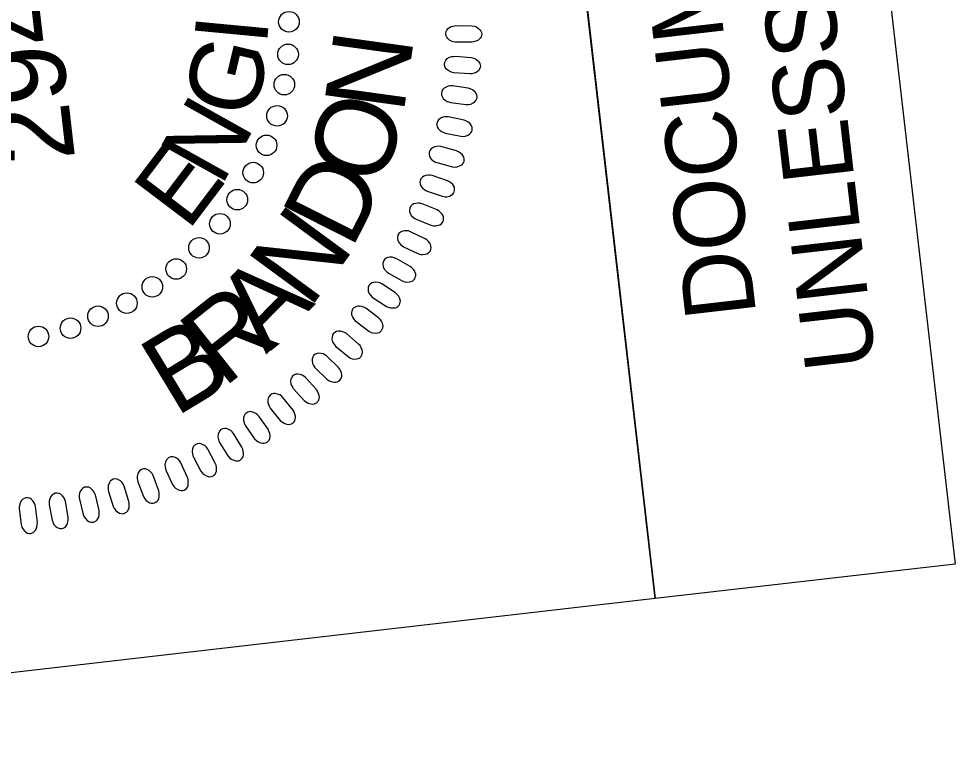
# Model space of a CAD drawing. Extents: x 477658 to 478938, y 495105 to 496902.
# Drawn here: x 477804.4 to 477877.3, y 496568.3 to 496626.4 of the extents above; entities that cross this region are included whole.
import ezdxf

# ---------------------------------------------------------------- set-up
doc = ezdxf.new("R2010")
doc.units = 0
for name, color, linetype in [('Sheet PE Seal Cell', 7, 'Continuous'), ('Sheet Plan CELL', 7, 'Continuous'), ('Sheet Sticker Exception Certification CELL', 7, 'Continuous')]:
    doc.layers.add(name, color=color, linetype=linetype)

msp = doc.modelspace()

# ---------------------------------------------------------------- linework, layer by layer
at = {"layer": 'Sheet PE Seal Cell'}
for points in [[(477838.441, 496625.837), (477839.667, 496625.823), (477839.886, 496625.783), (477840.025, 496625.729), (477840.194, 496625.615), (477840.302, 496625.517), (477840.381, 496625.404), (477840.419, 496625.299), (477840.438, 496625.186), (477840.417, 496625.075), (477840.386, 496624.955), (477840.325, 496624.851), (477840.223, 496624.748), (477840.143, 496624.689), (477839.993, 496624.623), (477839.813, 496624.565), (477839.653, 496624.545), (477838.397, 496624.551), (477838.227, 496624.576), (477838.088, 496624.623), (477837.93, 496624.713), (477837.791, 496624.827), (477837.713, 496624.925), (477837.654, 496625.083), (477837.636, 496625.233), (477837.678, 496625.382), (477837.729, 496625.486), (477837.83, 496625.612), (477838, 496625.729), (477838.181, 496625.795), (477838.311, 496625.823)], [(477838.388, 496623.449), (477839.611, 496623.358), (477839.827, 496623.305), (477839.963, 496623.242), (477840.124, 496623.118), (477840.225, 496623.012), (477840.297, 496622.895), (477840.329, 496622.788), (477840.34, 496622.674), (477840.312, 496622.564), (477840.273, 496622.447), (477840.206, 496622.347), (477840.099, 496622.25), (477840.015, 496622.196), (477839.861, 496622.14), (477839.677, 496622.094), (477839.516, 496622.083), (477838.263, 496622.169), (477838.095, 496622.204), (477837.96, 496622.259), (477837.807, 496622.36), (477837.676, 496622.482), (477837.603, 496622.585), (477837.556, 496622.746), (477837.547, 496622.897), (477837.598, 496623.042), (477837.655, 496623.144), (477837.763, 496623.263), (477837.942, 496623.369), (477838.126, 496623.423), (477838.257, 496623.443)], [(477838.009, 496619.86), (477839.224, 496619.692), (477839.445, 496619.7), (477839.592, 496619.732), (477839.775, 496619.82), (477839.897, 496619.901), (477839.991, 496620.002), (477840.045, 496620.1), (477840.08, 496620.208), (477840.075, 496620.322), (477840.062, 496620.445), (477840.018, 496620.556), (477839.933, 496620.673), (477839.862, 496620.744), (477839.723, 496620.83), (477839.553, 496620.914), (477839.398, 496620.958), (477838.154, 496621.138), (477837.983, 496621.138), (477837.839, 496621.112), (477837.669, 496621.045), (477837.515, 496620.954), (477837.423, 496620.868), (477837.342, 496620.721), (477837.302, 496620.576), (477837.321, 496620.421), (477837.356, 496620.311), (477837.437, 496620.172), (477837.589, 496620.03), (477837.758, 496619.939), (477837.882, 496619.892)], [(477837.607, 496617.465), (477838.81, 496617.222), (477839.032, 496617.215), (477839.179, 496617.238), (477839.368, 496617.314), (477839.495, 496617.388), (477839.595, 496617.483), (477839.655, 496617.576), (477839.697, 496617.683), (477839.699, 496617.797), (477839.694, 496617.92), (477839.656, 496618.034), (477839.578, 496618.157), (477839.512, 496618.231), (477839.379, 496618.327), (477839.215, 496618.421), (477839.063, 496618.475), (477837.833, 496618.731), (477837.662, 496618.743), (477837.517, 496618.726), (477837.343, 496618.67), (477837.184, 496618.588), (477837.086, 496618.508), (477836.996, 496618.367), (477836.947, 496618.224), (477836.956, 496618.069), (477836.985, 496617.957), (477837.057, 496617.813), (477837.199, 496617.662), (477837.362, 496617.56), (477837.483, 496617.506)], [(477836.964, 496615.168), (477838.149, 496614.849), (477838.371, 496614.828), (477838.519, 496614.842), (477838.712, 496614.907), (477838.843, 496614.972), (477838.949, 496615.06), (477839.015, 496615.15), (477839.063, 496615.254), (477839.073, 496615.367), (477839.075, 496615.491), (477839.045, 496615.607), (477838.975, 496615.734), (477838.914, 496615.812), (477838.787, 496615.916), (477838.629, 496616.02), (477838.481, 496616.084), (477837.269, 496616.417), (477837.1, 496616.439), (477836.953, 496616.431), (477836.776, 496616.387), (477836.612, 496616.315), (477836.509, 496616.241), (477836.411, 496616.106), (477836.353, 496615.966), (477836.353, 496615.812), (477836.374, 496615.698), (477836.437, 496615.549), (477836.57, 496615.39), (477836.726, 496615.278), (477836.843, 496615.216)], [(477836.206, 496612.939), (477837.368, 496612.547), (477837.588, 496612.512), (477837.737, 496612.517), (477837.934, 496612.569), (477838.069, 496612.626), (477838.18, 496612.706), (477838.252, 496612.792), (477838.306, 496612.893), (477838.323, 496613.005), (477838.333, 496613.128), (477838.31, 496613.246), (477838.248, 496613.378), (477838.192, 496613.46), (477838.072, 496613.572), (477837.921, 496613.686), (477837.777, 496613.758), (477836.589, 496614.167), (477836.421, 496614.199), (477836.274, 496614.201), (477836.094, 496614.168), (477835.926, 496614.106), (477835.82, 496614.039), (477835.713, 496613.91), (477835.646, 496613.774), (477835.636, 496613.62), (477835.65, 496613.505), (477835.703, 496613.353), (477835.826, 496613.186), (477835.975, 496613.064), (477836.088, 496612.995)], [(477835.343, 496610.766), (477836.478, 496610.302), (477836.695, 496610.253), (477836.845, 496610.248), (477837.044, 496610.288), (477837.183, 496610.337), (477837.299, 496610.41), (477837.375, 496610.492), (477837.436, 496610.589), (477837.46, 496610.699), (477837.478, 496610.821), (477837.462, 496610.941), (477837.409, 496611.076), (477837.358, 496611.161), (477837.245, 496611.28), (477837.101, 496611.404), (477836.962, 496611.485), (477835.802, 496611.967), (477835.637, 496612.01), (477835.49, 496612.022), (477835.309, 496611.999), (477835.137, 496611.949), (477835.026, 496611.889), (477834.911, 496611.766), (477834.837, 496611.635), (477834.817, 496611.482), (477834.823, 496611.366), (477834.867, 496611.21), (477834.979, 496611.036), (477835.12, 496610.905), (477835.228, 496610.829)], [(477834.366, 496608.622), (477835.471, 496608.088), (477835.684, 496608.025), (477835.833, 496608.011), (477836.035, 496608.038), (477836.175, 496608.078), (477836.296, 496608.144), (477836.378, 496608.221), (477836.444, 496608.314), (477836.475, 496608.423), (477836.501, 496608.544), (477836.492, 496608.664), (477836.448, 496608.801), (477836.402, 496608.89), (477836.297, 496609.016), (477836.162, 496609.148), (477836.028, 496609.238), (477834.9, 496609.792), (477834.738, 496609.846), (477834.593, 496609.866), (477834.41, 496609.855), (477834.235, 496609.815), (477834.121, 496609.762), (477833.998, 496609.647), (477833.916, 496609.521), (477833.887, 496609.369), (477833.886, 496609.253), (477833.92, 496609.096), (477834.02, 496608.914), (477834.153, 496608.775), (477834.256, 496608.692)], [(477833.18, 496606.571), (477834.249, 496605.968), (477834.458, 496605.893), (477834.606, 496605.87), (477834.809, 496605.884), (477834.952, 496605.915), (477835.077, 496605.973), (477835.163, 496606.044), (477835.235, 496606.133), (477835.273, 496606.24), (477835.305, 496606.359), (477835.305, 496606.48), (477835.269, 496606.62), (477835.23, 496606.711), (477835.132, 496606.843), (477835.005, 496606.983), (477834.878, 496607.081), (477833.787, 496607.705), (477833.628, 496607.769), (477833.484, 496607.798), (477833.302, 496607.799), (477833.124, 496607.771), (477833.008, 496607.725), (477832.878, 496607.618), (477832.787, 496607.497), (477832.748, 496607.347), (477832.741, 496607.231), (477832.764, 496607.072), (477832.854, 496606.885), (477832.977, 496606.737), (477833.076, 496606.648)], [(477831.993, 496604.641), (477833.022, 496603.972), (477833.226, 496603.884), (477833.371, 496603.851), (477833.575, 496603.853), (477833.72, 496603.875), (477833.848, 496603.925), (477833.939, 496603.991), (477834.017, 496604.075), (477834.06, 496604.179), (477834.1, 496604.296), (477834.107, 496604.416), (477834.08, 496604.559), (477834.047, 496604.652), (477833.958, 496604.79), (477833.84, 496604.938), (477833.719, 496605.044), (477832.669, 496605.735), (477832.515, 496605.809), (477832.373, 496605.847), (477832.191, 496605.859), (477832.013, 496605.842), (477831.892, 496605.803), (477831.757, 496605.704), (477831.659, 496605.59), (477831.611, 496605.443), (477831.596, 496605.327), (477831.61, 496605.167), (477831.687, 496604.975), (477831.801, 496604.819), (477831.893, 496604.724)], [(477830.666, 496602.787), (477831.651, 496602.055), (477831.849, 496601.954), (477831.992, 496601.913), (477832.195, 496601.901), (477832.342, 496601.914), (477832.473, 496601.956), (477832.566, 496602.016), (477832.65, 496602.095), (477832.7, 496602.196), (477832.748, 496602.311), (477832.763, 496602.43), (477832.745, 496602.573), (477832.717, 496602.669), (477832.637, 496602.813), (477832.528, 496602.967), (477832.414, 496603.081), (477831.41, 496603.837), (477831.261, 496603.92), (477831.121, 496603.967), (477830.94, 496603.99), (477830.762, 496603.984), (477830.639, 496603.953), (477830.497, 496603.863), (477830.392, 496603.755), (477830.335, 496603.611), (477830.313, 496603.497), (477830.316, 496603.336), (477830.382, 496603.139), (477830.486, 496602.977), (477830.572, 496602.876)], [(477829.099, 496600.86), (477830.035, 496600.067), (477830.226, 496599.954), (477830.367, 496599.903), (477830.569, 496599.879), (477830.715, 496599.883), (477830.849, 496599.917), (477830.947, 496599.971), (477831.035, 496600.044), (477831.092, 496600.143), (477831.146, 496600.253), (477831.168, 496600.371), (477831.159, 496600.516), (477831.137, 496600.613), (477831.067, 496600.761), (477830.968, 496600.923), (477830.861, 496601.043), (477829.907, 496601.86), (477829.763, 496601.953), (477829.627, 496602.008), (477829.448, 496602.044), (477829.268, 496602.048), (477829.145, 496602.025), (477828.997, 496601.944), (477828.886, 496601.842), (477828.82, 496601.703), (477828.79, 496601.591), (477828.784, 496601.429), (477828.836, 496601.229), (477828.93, 496601.061), (477829.01, 496600.955)], [(477827.513, 496599.157), (477828.398, 496598.307), (477828.581, 496598.182), (477828.719, 496598.123), (477828.919, 496598.086), (477829.065, 496598.08), (477829.2, 496598.106), (477829.301, 496598.154), (477829.394, 496598.221), (477829.456, 496598.315), (477829.518, 496598.423), (477829.548, 496598.539), (477829.548, 496598.684), (477829.532, 496598.782), (477829.47, 496598.935), (477829.382, 496599.102), (477829.283, 496599.229), (477828.382, 496600.105), (477828.244, 496600.206), (477828.112, 496600.27), (477827.935, 496600.316), (477827.756, 496600.332), (477827.632, 496600.317), (477827.48, 496600.245), (477827.362, 496600.151), (477827.288, 496600.016), (477827.251, 496599.906), (477827.234, 496599.745), (477827.274, 496599.541), (477827.357, 496599.368), (477827.43, 496599.257)], [(477825.804, 496597.547), (477826.635, 496596.643), (477826.81, 496596.507), (477826.943, 496596.439), (477827.141, 496596.39), (477827.286, 496596.375), (477827.423, 496596.392), (477827.526, 496596.434), (477827.624, 496596.495), (477827.692, 496596.585), (477827.76, 496596.688), (477827.797, 496596.803), (477827.806, 496596.947), (477827.796, 496597.047), (477827.745, 496597.202), (477827.667, 496597.375), (477827.576, 496597.508), (477826.732, 496598.438), (477826.6, 496598.548), (477826.473, 496598.62), (477826.299, 496598.677), (477826.122, 496598.704), (477825.996, 496598.698), (477825.84, 496598.636), (477825.716, 496598.549), (477825.634, 496598.418), (477825.59, 496598.311), (477825.563, 496598.151), (477825.591, 496597.946), (477825.662, 496597.768), (477825.728, 496597.652)], [(477823.989, 496596.053), (477824.761, 496595.098), (477824.927, 496594.951), (477825.055, 496594.876), (477825.25, 496594.814), (477825.394, 496594.79), (477825.531, 496594.799), (477825.638, 496594.833), (477825.738, 496594.888), (477825.812, 496594.975), (477825.886, 496595.073), (477825.93, 496595.185), (477825.949, 496595.329), (477825.945, 496595.428), (477825.903, 496595.587), (477825.837, 496595.764), (477825.754, 496595.902), (477824.97, 496596.884), (477824.846, 496597.002), (477824.722, 496597.082), (477824.553, 496597.15), (477824.378, 496597.188), (477824.252, 496597.189), (477824.092, 496597.137), (477823.964, 496597.058), (477823.873, 496596.933), (477823.823, 496596.829), (477823.786, 496596.671), (477823.8, 496596.464), (477823.861, 496596.282), (477823.919, 496596.163)], [(477822.06, 496594.666), (477822.77, 496593.665), (477822.927, 496593.509), (477823.051, 496593.425), (477823.24, 496593.351), (477823.384, 496593.318), (477823.521, 496593.318), (477823.629, 496593.346), (477823.733, 496593.395), (477823.812, 496593.476), (477823.892, 496593.57), (477823.943, 496593.679), (477823.971, 496593.821), (477823.973, 496593.921), (477823.942, 496594.081), (477823.886, 496594.262), (477823.813, 496594.406), (477823.092, 496595.435), (477822.975, 496595.56), (477822.857, 496595.648), (477822.692, 496595.726), (477822.52, 496595.775), (477822.394, 496595.784), (477822.232, 496595.742), (477822.098, 496595.671), (477822, 496595.552), (477821.943, 496595.451), (477821.897, 496595.296), (477821.898, 496595.089), (477821.947, 496594.903), (477821.997, 496594.78)], [(477820.045, 496593.38), (477820.691, 496592.336), (477820.839, 496592.17), (477820.957, 496592.078), (477821.141, 496591.994), (477821.282, 496591.951), (477821.419, 496591.942), (477821.529, 496591.964), (477821.635, 496592.006), (477821.719, 496592.082), (477821.805, 496592.17), (477821.863, 496592.276), (477821.899, 496592.416), (477821.909, 496592.515), (477821.887, 496592.678), (477821.843, 496592.862), (477821.778, 496593.009), (477821.123, 496594.082), (477821.015, 496594.214), (477820.903, 496594.309), (477820.743, 496594.397), (477820.574, 496594.458), (477820.449, 496594.474), (477820.284, 496594.443), (477820.146, 496594.381), (477820.041, 496594.268), (477819.978, 496594.17), (477819.922, 496594.019), (477819.911, 496593.812), (477819.947, 496593.624), (477819.99, 496593.498)], [(477818.004, 496592.239), (477818.582, 496591.157), (477818.719, 496590.981), (477818.831, 496590.882), (477819.01, 496590.786), (477819.148, 496590.735), (477819.284, 496590.718), (477819.394, 496590.732), (477819.503, 496590.767), (477819.592, 496590.838), (477819.684, 496590.921), (477819.748, 496591.022), (477819.793, 496591.16), (477819.808, 496591.258), (477819.797, 496591.423), (477819.764, 496591.608), (477819.709, 496591.76), (477819.123, 496592.871), (477819.023, 496593.011), (477818.918, 496593.112), (477818.764, 496593.21), (477818.599, 496593.281), (477818.475, 496593.305), (477818.308, 496593.284), (477818.167, 496593.231), (477818.055, 496593.125), (477817.986, 496593.032), (477817.92, 496592.884), (477817.896, 496592.678), (477817.921, 496592.488), (477817.956, 496592.36)], [(477815.868, 496591.229), (477816.378, 496590.113), (477816.503, 496589.929), (477816.608, 496589.823), (477816.781, 496589.716), (477816.915, 496589.656), (477817.05, 496589.631), (477817.162, 496589.638), (477817.272, 496589.666), (477817.365, 496589.731), (477817.462, 496589.808), (477817.532, 496589.906), (477817.586, 496590.04), (477817.608, 496590.137), (477817.606, 496590.301), (477817.586, 496590.49), (477817.54, 496590.644), (477817.025, 496591.79), (477816.934, 496591.935), (477816.835, 496592.043), (477816.687, 496592.151), (477816.527, 496592.231), (477816.406, 496592.264), (477816.238, 496592.253), (477816.094, 496592.209), (477815.974, 496592.11), (477815.9, 496592.022), (477815.826, 496591.878), (477815.788, 496591.674), (477815.801, 496591.483), (477815.828, 496591.353)], [(477813.674, 496590.318), (477814.113, 496589.172), (477814.226, 496588.981), (477814.325, 496588.868), (477814.49, 496588.75), (477814.62, 496588.683), (477814.754, 496588.649), (477814.865, 496588.649), (477814.978, 496588.67), (477815.075, 496588.729), (477815.175, 496588.799), (477815.252, 496588.892), (477815.314, 496589.024), (477815.342, 496589.119), (477815.351, 496589.283), (477815.342, 496589.472), (477815.306, 496589.629), (477814.864, 496590.805), (477814.783, 496590.956), (477814.69, 496591.07), (477814.55, 496591.187), (477814.395, 496591.277), (477814.276, 496591.317), (477814.108, 496591.317), (477813.961, 496591.282), (477813.836, 496591.191), (477813.756, 496591.107), (477813.672, 496590.968), (477813.622, 496590.768), (477813.623, 496590.575), (477813.642, 496590.444)], [(477811.403, 496589.573), (477811.769, 496588.402), (477811.87, 496588.204), (477811.961, 496588.086), (477812.12, 496587.957), (477812.245, 496587.882), (477812.376, 496587.839), (477812.487, 496587.833), (477812.601, 496587.847), (477812.701, 496587.899), (477812.806, 496587.964), (477812.889, 496588.052), (477812.959, 496588.179), (477812.992, 496588.272), (477813.012, 496588.435), (477813.015, 496588.625), (477812.989, 496588.783), (477812.621, 496589.985), (477812.549, 496590.14), (477812.465, 496590.26), (477812.332, 496590.385), (477812.183, 496590.485), (477812.066, 496590.533), (477811.899, 496590.543), (477811.75, 496590.517), (477811.619, 496590.435), (477811.534, 496590.356), (477811.443, 496590.223), (477811.379, 496590.025), (477811.369, 496589.833), (477811.379, 496589.701)], [(477806.785, 496588.539), (477807.001, 496587.331), (477807.077, 496587.122), (477807.152, 496586.994), (477807.293, 496586.847), (477807.408, 496586.755), (477807.533, 496586.697), (477807.642, 496586.676), (477807.757, 496586.677), (477807.863, 496586.716), (477807.976, 496586.767), (477808.068, 496586.844), (477808.153, 496586.961), (477808.198, 496587.05), (477808.238, 496587.208), (477808.265, 496587.396), (477808.259, 496587.556), (477808.045, 496588.795), (477807.993, 496588.958), (477807.924, 496589.087), (477807.807, 496589.229), (477807.673, 496589.346), (477807.563, 496589.408), (477807.398, 496589.439), (477807.247, 496589.432), (477807.107, 496589.367), (477807.013, 496589.299), (477806.905, 496589.179), (477806.818, 496588.991), (477806.783, 496588.802), (477806.776, 496588.669)], [(477809.131, 496588.975), (477809.423, 496587.784), (477809.512, 496587.58), (477809.595, 496587.456), (477809.745, 496587.318), (477809.865, 496587.235), (477809.993, 496587.184), (477810.104, 496587.171), (477810.218, 496587.178), (477810.322, 496587.224), (477810.431, 496587.281), (477810.519, 496587.364), (477810.596, 496587.486), (477810.636, 496587.578), (477810.666, 496587.739), (477810.681, 496587.928), (477810.665, 496588.088), (477810.373, 496589.31), (477810.311, 496589.469), (477810.234, 496589.594), (477810.109, 496589.728), (477809.968, 496589.837), (477809.854, 496589.892), (477809.687, 496589.912), (477809.537, 496589.896), (477809.401, 496589.822), (477809.312, 496589.748), (477809.211, 496589.621), (477809.136, 496589.428), (477809.114, 496589.238), (477809.115, 496589.105)], [(477804.449, 496588.217), (477804.589, 496586.998), (477804.651, 496586.785), (477804.719, 496586.652), (477804.85, 496586.496), (477804.959, 496586.398), (477805.08, 496586.332), (477805.188, 496586.304), (477805.302, 496586.297), (477805.41, 496586.33), (477805.526, 496586.373), (477805.623, 496586.444), (477805.716, 496586.556), (477805.766, 496586.642), (477805.816, 496586.798), (477805.855, 496586.983), (477805.859, 496587.144), (477805.723, 496588.394), (477805.681, 496588.559), (477805.62, 496588.693), (477805.513, 496588.841), (477805.386, 496588.967), (477805.28, 496589.035), (477805.117, 496589.077), (477804.966, 496589.079), (477804.822, 496589.022), (477804.725, 496588.961), (477804.609, 496588.848), (477804.51, 496588.666), (477804.464, 496588.48), (477804.449, 496588.347)]]:
    msp.add_lwpolyline(points, close=True, dxfattribs=at)
for centre in [(477825.438, 496626.133), (477825.368, 496623.6), (477825.078, 496621.242), (477824.515, 496618.813), (477823.697, 496616.515), (477822.658, 496614.391), (477821.416, 496612.285), (477820.068, 496610.407), (477818.439, 496608.536), (477816.663, 496606.889), (477814.806, 496605.499), (477812.827, 496604.229), (477810.579, 496603.209), (477808.44, 496602.282), (477805.948, 496601.635)]:
    msp.add_circle(centre, 0.801, dxfattribs=at)
at = {"layer": 'Sheet Plan CELL'}
msp.add_lwpolyline([(477742.203, 496568.327), (477730.743, 496667.719), (477842.515, 496680.606), (477853.949, 496581.224)], close=True, dxfattribs=at)
at = {"layer": 'Sheet Sticker Exception Certification CELL'}
for p, q in [((477854.381, 496782.637), (477877.294, 496583.916)), ((477854.381, 496782.637), (477877.294, 496583.916)), ((477853.949, 496581.224), (477831.036, 496779.945)), ((477853.949, 496581.224), (477831.036, 496779.945)), ((477877.294, 496583.916), (477853.949, 496581.224)), ((477877.294, 496583.916), (477853.949, 496581.224))]:
    msp.add_line(p, q, dxfattribs=at)

# ---------------------------------------------------------------- texts
at = {"layer": 'Sheet PE Seal Cell'}
for s, height, rotation, p in [('29470', 6.2363, 96.55865, (477808.808, 496615.429)), ('I', 5.669, 84.60206, (477823.702, 496624.221)), ('G', 5.669, 76.66226, (477822.668, 496618.436)), ('N', 6.236, 82.12779, (477834.352, 496618.889)), ('N', 5.669, 60.78267, (477820.151, 496613.219)), ('O', 6.236, 72.02794, (477832.632, 496613.102)), ('E', 5.669, 52.84287, (477817.574, 496609.766)), ('D', 6.236, 63.15972, (477830.304, 496608.338)), ('N', 6.236, 53.67003, (477827.032, 496603.703)), ('A', 6.236, 45.55885, (477823.662, 496600.214)), ('R', 6.236, 38.44201, (477820.324, 496597.572)), ('B', 6.236, 31.16698, (477816.601, 496595.32))]:
    msp.add_text(s, height=height, rotation=rotation, dxfattribs=at).set_placement(p)
at = {"layer": 'Sheet Sticker Exception Certification CELL'}
for s, p in [('UNLESS ALL SIGNATURES COMPLETED', (477871.135, 496599.312)), ('UNLESS ALL SIGNATURES COMPLETED', (477871.135, 496599.312)), ('DOCUMENT NOT CONSIDERED FINAL', (477861.813, 496603.341)), ('DOCUMENT NOT CONSIDERED FINAL', (477861.813, 496603.341))]:
    msp.add_text(s, height=5.5, rotation=96.57729, dxfattribs=at).set_placement(p)

doc.saveas('drawing.dxf')
